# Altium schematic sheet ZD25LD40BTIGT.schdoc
size 127 x 101 mm
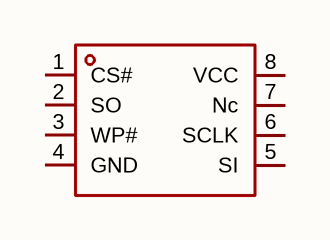
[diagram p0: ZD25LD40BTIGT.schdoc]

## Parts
U?  zd25ld40btigt  [SOP-8_L4.9-W3.9-P1.27-LS6.0-BL]  (value not drawn)

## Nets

Not connected (* = marked no-connect by the designer): U? 1(CS#) 2(SO) 3(WP#) 4(GND) 5(SI) 6(SCLK) 7(Nc) 8(VCC)

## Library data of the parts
U? = zd25ld40btigt: 接口类型:SPI;存储容量:4Mbit;时钟频率(fc):85MHz;; Manufacturer: Zetta(澜智); AddInBom: yes; ModelId: 75c24a7891ee4dd6bdac16a7163ff87e; ModelName: SOP-8_L4.9-W3.9-P1.27-LS6.0-BL-1; ModelTransform: 192.913,236.22,0,0,0,0,-0.393,2.749,0; Interface: SPI; Memory Size: 4Mbit; Clock Frequency: 85MHz; Voltage - Supply: 1.65V~2.1V; Standby Supply Current: 9uA; Program / Erase Cycles: 100000次; Page Programming Time (Tpp): 1.6ms; Block Erase Time(tBE): 10ms; Data Retention - TDR (Year): 20年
